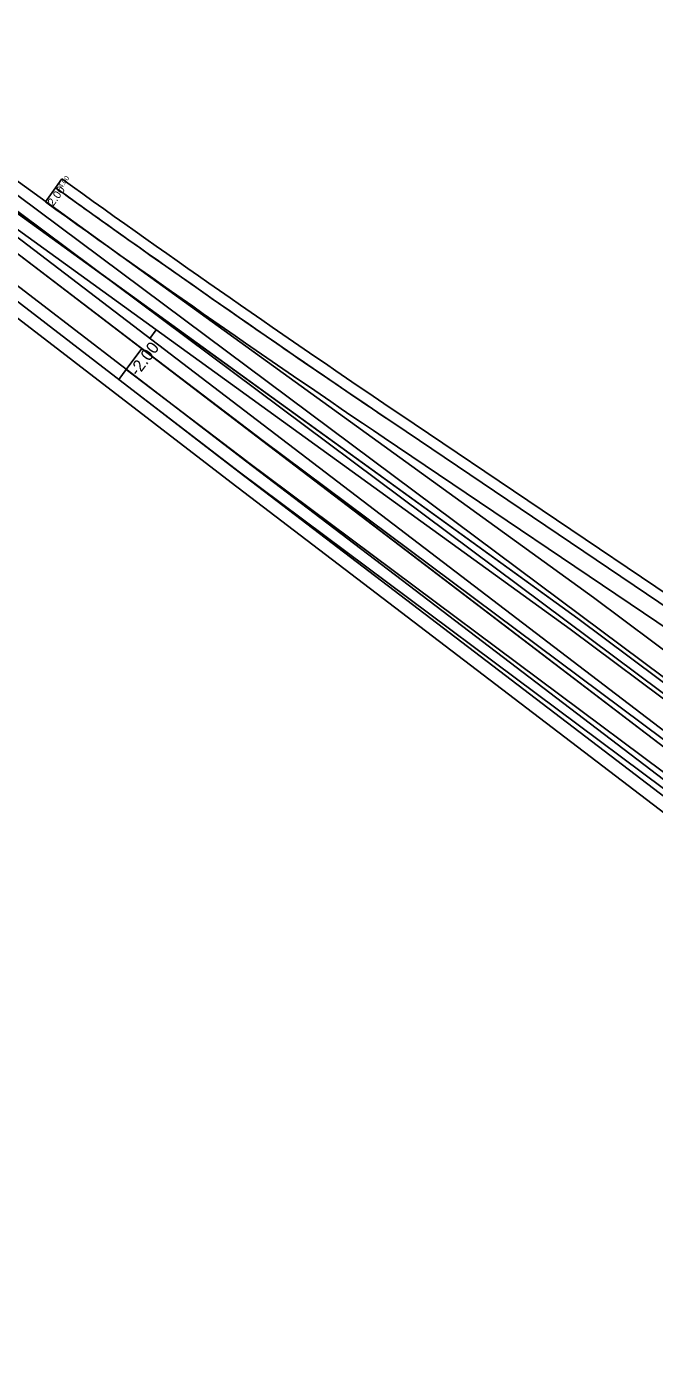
# Model space of a CAD drawing. Extents: x 2342222 to 2351711, y 366548 to 372860.
# Drawn here: x 2343637 to 2344214, y 370762 to 371981 of the extents above; entities that cross this region are included whole.
import ezdxf

# ---------------------------------------------------------------- set-up
doc = ezdxf.new("R2010")
doc.units = 0
for name, color, linetype in [('RD_PD_PaveShd', 7, 'Continuous'), ('RD_PD_SuperShp_BL_EB_526', 7, 'Continuous'), ('RD_PD_SuperShp_BL_WB_526', 7, 'Continuous'), ('RD_PD_SuperShp_EB_526', 7, 'Continuous'), ('RD_PD_SuperShp_LINE-A', 7, 'Continuous'), ('RD_PD_SuperShp_WB_526', 7, 'Continuous')]:
    doc.layers.add(name, color=color, linetype=linetype)

msp = doc.modelspace()

# ---------------------------------------------------------------- linework, layer by layer
at = {"layer": 'RD_PD_PaveShd'}
for p, q in [((2343437.7, 371931.9), (2344136.5, 371426.7)), ((2343749.9, 371694.1), (2343755.7, 371702)), ((2344136.5, 371426.7), (2345306.6, 370553.4))]:
    msp.add_line(p, q, dxfattribs=at)
at = {"layer": 'RD_PD_SuperShp_BL_EB_526'}
for p, q in [((2344441, 371166.6), (2343459.8, 371915.6)), ((2343465, 371896.5), (2343853.9, 371599.7)), ((2343465, 371896.5), (2344433.7, 371157)), ((2343839.3, 371580.6), (2343451.3, 371878.1)), ((2343454.2, 371861.9), (2343832.1, 371571)), ((2343832.1, 371571), (2343455.8, 371860.7)), ((2343839.3, 371580.6), (2343460.9, 371870.7)), ((2343580.7, 371749.4), (2343824.8, 371561.5)), ((2343853.9, 371599.7), (2344433.7, 371157)), ((2344419.3, 371137.9), (2343839.3, 371580.6)), ((2344419.3, 371137.9), (2343839.3, 371580.6)), ((2343832.1, 371571), (2344412.1, 371128.3)), ((2344412.1, 371128.3), (2343832.1, 371571)), ((2343824.8, 371561.5), (2344404.8, 371118.7))]:
    msp.add_line(p, q, dxfattribs=at)
at = {"layer": 'RD_PD_SuperShp_BL_WB_526'}
for p, q in [((2343437.7, 371931.9), (2344136.5, 371426.7)), ((2343444.9, 371941.5), (2344143.6, 371436.4)), ((2344143.6, 371436.4), (2343444.9, 371941.5)), ((2345328.2, 370582.3), (2344157.9, 371455.7)), ((2344143.6, 371436.4), (2345313.8, 370563)), ((2345236.9, 370620.4), (2344143.6, 371436.4)), ((2344136.5, 371426.7), (2345229.7, 370610.8))]:
    msp.add_line(p, q, dxfattribs=at)
msp.add_lwpolyline([(2344157.9, 371455.7), (2343532.6, 371907.7), (2343458.6, 371959.9)], dxfattribs=at)
at = {"layer": 'RD_PD_SuperShp_EB_526'}
for p, q in [((2343742.7, 371684.8), (2343728.4, 371665.5)), ((2343854.1, 371599.9), (2343742.7, 371684.8)), ((2343728.4, 371665.5), (2343721.5, 371656.4)), ((2343728.4, 371665.5), (2343839.6, 371580.8)), ((2343839.6, 371580.8), (2343728.4, 371665.5)), ((2343721.5, 371656.4), (2343832.6, 371571)), ((2345288.6, 370529.2), (2343854.1, 371599.9)), ((2343839.6, 371580.8), (2343839.6, 371580.8)), ((2344362.1, 371190.8), (2343839.8, 371580.6)), ((2343839.8, 371580.6), (2343839.8, 371580.6)), ((2343839.8, 371580.6), (2344362.1, 371190.8)), ((2343832.6, 371571), (2344354.6, 371181.4))]:
    msp.add_line(p, q, dxfattribs=at)
at = {"layer": 'RD_PD_SuperShp_LINE-A'}
for p, q in [((2343669.2, 371840.7), (2343663.4, 371832.6)), ((2343663.4, 371832.6), (2343654, 371819.6)), ((2343974.3, 371616), (2344345.7, 371365.3)), ((2344345.7, 371365.3), (2343974.3, 371616)), ((2344351.3, 371373.6), (2343979.9, 371624.3)), ((2343965.4, 371602.8), (2344336.8, 371352.1)), ((2343965.4, 371602.8), (2344336.8, 371352.1))]:
    msp.add_line(p, q, dxfattribs=at)
for radius, start, end in [(12990, 234.31228, 235.9825), (13000, 234.31228, 235.9825), (13000, 234.31228, 234.54147), (13016, 234.31228, 235.9825), (13000, 234.54147, 234.9822), (13000, 234.9822, 235.42294), (13000, 235.42294, 235.86368), (13000, 235.86368, 235.9825)]:
    msp.add_arc((2351247.1, 382391.3), radius, start, end, dxfattribs=at)
at = {"layer": 'RD_PD_SuperShp_WB_526'}
for p, q in [((2342239.6, 372847.3), (2345207.1, 370632.5)), ((2345214.3, 370642.1), (2342246.7, 372856.9))]:
    msp.add_line(p, q, dxfattribs=at)

# ---------------------------------------------------------------- texts
at = {"layer": 'RD_PD_SuperShp_EB_526'}
msp.add_text('-2.00', height=11.04, rotation=53.2637, dxfattribs=at).set_placement((2343739.1, 371658.6))
at = {"layer": 'RD_PD_SuperShp_LINE-A'}
for s, height, p in [('-4.00', 4.6, (2343667.9, 371829.8)), ('2.00', 7.36, (2343661.3, 371815.2))]:
    msp.add_text(s, height=height, rotation=54.3123, dxfattribs=at).set_placement(p)

doc.saveas('drawing.dxf')
